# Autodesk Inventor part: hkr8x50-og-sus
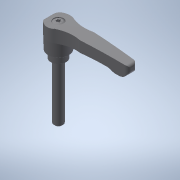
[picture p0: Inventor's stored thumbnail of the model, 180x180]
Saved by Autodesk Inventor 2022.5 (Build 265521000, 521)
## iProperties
Created: 2017-09
Part Number: hkr8x50-og-sus
Material: 一般
Document SubType Name: Modeling
Designer: imaocorp
Density: 1 g/cm^3
Appearance: 既定
Author: imaocorp
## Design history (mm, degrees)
node "hkr8x50-og-sus.x_t1"
node "hkr8x50-og-sus"
node "Base1"
